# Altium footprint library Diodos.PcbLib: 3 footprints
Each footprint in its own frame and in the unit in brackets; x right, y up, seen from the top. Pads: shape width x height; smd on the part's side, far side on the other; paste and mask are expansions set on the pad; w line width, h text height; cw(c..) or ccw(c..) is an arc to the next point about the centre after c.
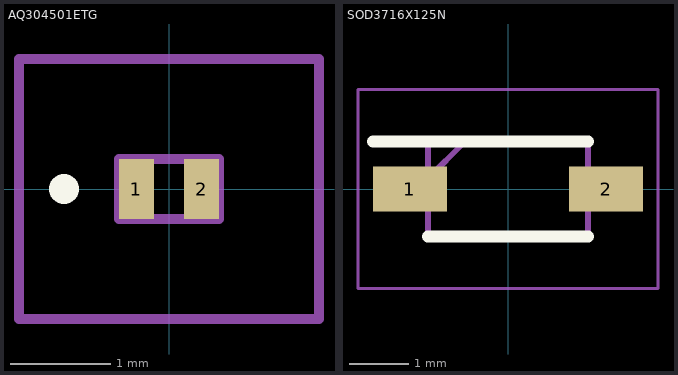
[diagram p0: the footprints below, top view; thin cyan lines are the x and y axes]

## AQ304501ETG [mm]
pads (2):
  rect 0.35x0.6 smd: 1(-0.325,0) 2(0.325,0)
Top Overlay:
  lines w0.2: -1.1,0 cw(c-1.05,0) -1,0 ; -1.1,0 ccw(c-1.05,0) -1,0 ; -1.1,0 cw(c-1.05,0) -1,0
Mechanical 13:
  lines w0.1: -0.5,-0.3 0.5,-0.3 0.5,0.3 -0.5,0.3 -0.5,-0.3
Mechanical 15:
  lines w0.1: -1.5,-1.3 1.5,-1.3 1.5,1.3 -1.5,1.3 -1.5,-1.3
3D body "AQ3045-01ETG.stp": height 0.43, standoff 0, extent -0.535,-0.34 0.535,0.335

## PCBComponent_1 [mm]

## SOD3716X125N [mm]
pads (2):
  rect 1.25x0.75 smd: 1(-1.65,0) 2(1.65,0)
Top Overlay:
  lines w0.2: -2.275,0.8 1.35,0.8 ; -1.35,-0.8 1.35,-0.8
Mechanical 13:
  lines w0.1: -1.35,0.175 -0.725,0.8 ; -1.35,-0.8 -1.35,0.8 1.35,0.8 1.35,-0.8 -1.35,-0.8
Mechanical 15:
  lines w0.05: -2.525,-1.675 -2.525,1.675 2.525,1.675 2.525,-1.675 -2.525,-1.675
3D body "1N5819HW-7-F.stp": height 1.25, standoff 0.06, extent -1.35,-0.8 1.35,0.8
